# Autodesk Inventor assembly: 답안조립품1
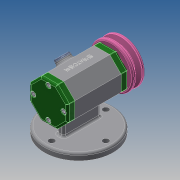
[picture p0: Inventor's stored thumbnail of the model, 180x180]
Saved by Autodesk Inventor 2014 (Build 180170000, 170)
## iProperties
Created: 2021-02
Part Number: 답안조립품1
Document SubType Name: Assembly
Designer: kb542-22
Author: kb542-22
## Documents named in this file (14)
- C:\Users\kb542-22\Desktop\답안조립품1.iam
- C:\Users\kb542-22\Desktop\본체.ipt
- C:\Users\kb542-22\Desktop\710204V1020\V벨트풀리.ipt
- C:\Users\kb542-22\Desktop\710204V1020\고무캡.ipt
- C:\Users\kb542-22\Desktop\710204V1020\너트 M8.ipt
- C:\Users\kb542-22\Desktop\710204V1020\뒤커버.ipt
- C:\Users\kb542-22\Desktop\710204V1020\베어링 15 x 32 x 9.ipt
- C:\Users\kb542-22\Desktop\710204V1020\볼트 M4 x 12.ipt
- C:\Users\kb542-22\Desktop\710204V1020\스프링와셔 8.ipt
- C:\Users\kb542-22\Desktop\710204V1020\앞커버.ipt
- C:\Users\kb542-22\Desktop\710204V1020\오일 실 15 25 7.ipt
- C:\Users\kb542-22\Desktop\710204V1020\와셔 8x17.ipt
- C:\Users\kb542-22\Desktop\710204V1020\축.ipt
- C:\Users\kb542-22\Desktop\710204V1020\키 3 x 3 x 12.ipt
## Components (2 placed, 2 different names)
1. V벨트풀리:1 — 각도:1
2. 고무캡:1 — 각도:1
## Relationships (1: Angle 1)
- 각도:1 [Angle]: V벨트풀리:1 ↔ 고무캡:1
